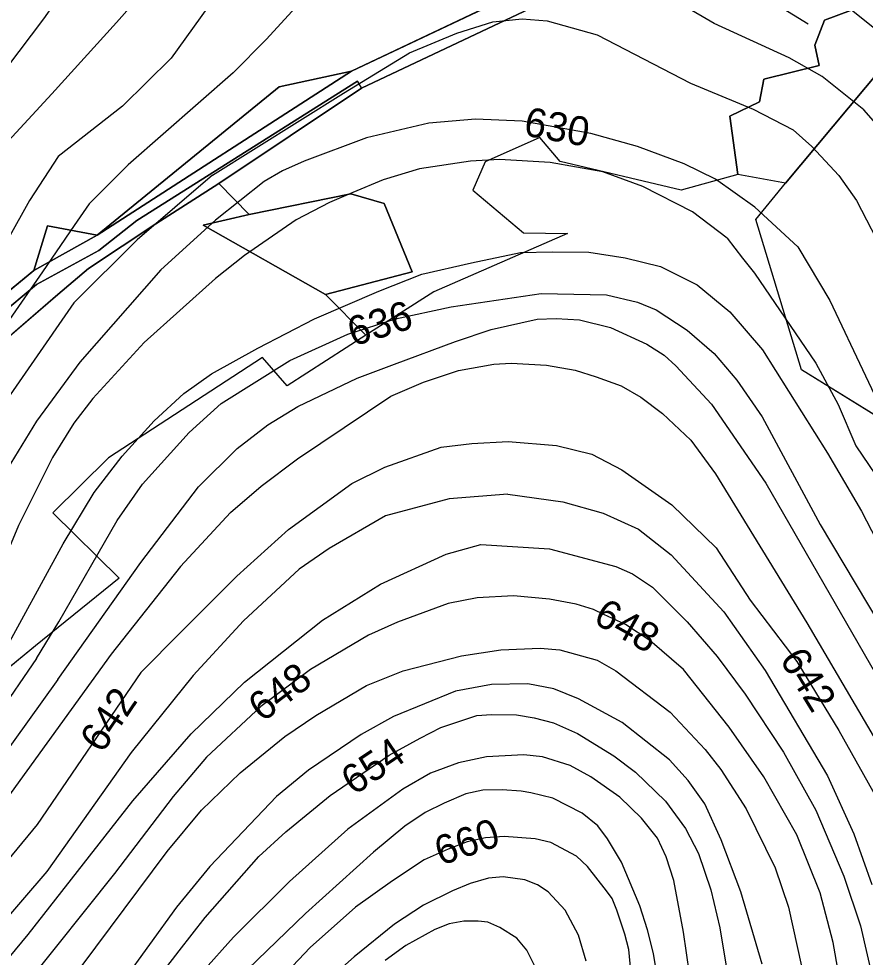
# Model space of a CAD drawing. Extents: x -709418 to -703832, y -1161719 to -1157826.
# Drawn here: x -706614.7 to -706381.5, y -1159816.4 to -1159557.8 of the extents above; entities that cross this region are included whole.
import ezdxf

# ---------------------------------------------------------------- set-up
doc = ezdxf.new("R2010")
doc.units = 0
for name, color, linetype in [('102_obvod PÚ', 7, 'Continuous'), ('120_vrstevnice hlavní', 7, 'Continuous'), ('121_vrstevnice hlavní_popis', 7, 'Continuous'), ('122_vrstevnice základní', 7, 'Continuous'), ('124_vrstevnice doplňková', 7, 'Continuous'), ('201_orná půda_KN', 7, 'Continuous'), ('206_TTP_KN', 7, 'Continuous'), ('210_ostatní plocha_KN', 7, 'Continuous')]:
    doc.layers.add(name, color=color, linetype=linetype)

msp = doc.modelspace()

# ---------------------------------------------------------------- linework, layer by layer
at = {"layer": '102_obvod PÚ'}
msp.add_lwpolyline([(-706367.74, -1159673.93), (-706399.11, -1159654.57), (-706411.64, -1159613.17), (-706403.46, -1159603.15), (-706416.61, -1159600.76), (-706432.22, -1159605.07), (-706465.56, -1159597.19), (-706471.14, -1159590.54), (-706486.23, -1159597.28), (-706489.67, -1159605.09), (-706475.68, -1159616.83), (-706463.55, -1159617.01), (-706500.37, -1159633.07), (-706519.13, -1159645.05), (-706540.75, -1159658.99), (-706547.56, -1159651.15), (-706589.97, -1159678.86), (-706605.34, -1159693.95), (-706587.09, -1159711.95), (-706610.14, -1159730.65), (-706648.39, -1159762.04), (-706648.03, -1159765), (-706661.44, -1159800.87), (-706686.33, -1159816.5)], dxfattribs=at)
at = {"layer": '120_vrstevnice hlavní'}
for points in [[(-706599.36, -1159545.61), (-706607.91, -1159557.89), (-706618.07, -1159571.37), (-706627.76, -1159583.84), (-706633.92, -1159592.08)], [(-706400.14, -1159620.68), (-706411.94, -1159609.75), (-706422.82, -1159602.06), (-706431.4, -1159597.76), (-706444.27, -1159593.05), (-706457.15, -1159589.47), (-706476.02, -1159586.04), (-706488.89, -1159585.47), (-706501.77, -1159586.61), (-706518.93, -1159590.61), (-706536.09, -1159597.05), (-706542.04, -1159599.71), (-706547.11, -1159602.7)], [(-706547.12, -1159602.7), (-706560.51, -1159613.3), (-706575.59, -1159626.97), (-706597.91, -1159652.48), (-706609.82, -1159668.71), (-706620.07, -1159685.26), (-706632.37, -1159707.7), (-706641.94, -1159724.9), (-706657.08, -1159747.29)], [(-706400.14, -1159620.68), (-706391.3, -1159635.45), (-706371.6, -1159676.97), (-706361.48, -1159695.78), (-706344.24, -1159720.85), (-706336.54, -1159733.39), (-706326.43, -1159752.2), (-706314.46, -1159777.28), (-706302.34, -1159796.09), (-706274.94, -1159816.35)], [(-706570.14, -1159708.76), (-706556.42, -1159693.85), (-706547.96, -1159686.64), (-706537.98, -1159679.11), (-706512.24, -1159661.86), (-706503.26, -1159658.01), (-706493.57, -1159654.74), (-706483.88, -1159653.03), (-706479.04, -1159652.74), (-706469.35, -1159653.31), (-706461.46, -1159654.68), (-706455.67, -1159656.45), (-706448.79, -1159658.94), (-706443.36, -1159662.08), (-706437.43, -1159666.56), (-706429.59, -1159673.97), (-706422.75, -1159683.24), (-706397.67, -1159724.27), (-706360.2, -1159788.11)], [(-706570.14, -1159708.76), (-706589.23, -1159732.95), (-706617.97, -1159772.72), (-706625.38, -1159783.55), (-706646.47, -1159811.2), (-706651.31, -1159815.9), (-706667.19, -1159827.83)], [(-706601.3, -1159824.16), (-706573.8, -1159787.26), (-706564.39, -1159775.86), (-706553.7, -1159765.6), (-706541.45, -1159755.62), (-706532.9, -1159749.78), (-706518.94, -1159741.52), (-706508.82, -1159737.53), (-706492.72, -1159733.39), (-706481.89, -1159731.68), (-706471.06, -1159731.26), (-706465.64, -1159731.68), (-706455.38, -1159734.53), (-706450.25, -1159737.53), (-706435.29, -1159748.93), (-706425.6, -1159759.19), (-706421.33, -1159764.74), (-706414.34, -1159775.57), (-706406.36, -1159791.82), (-706402.66, -1159802.65), (-706399.1, -1159818.89)], [(-706445.12, -1159830.57), (-706446.69, -1159814.33), (-706447.73, -1159810.04), (-706449.97, -1159803.5), (-706451.22, -1159800.26), (-706452.82, -1159798.09), (-706458.09, -1159791.39), (-706461.05, -1159788.6), (-706468.16, -1159784.84), (-706472.48, -1159783.84), (-706481.03, -1159783.12), (-706486.16, -1159783.55), (-706491.16, -1159784.59), (-706496.42, -1159786.69), (-706503.06, -1159789.61), (-706511.81, -1159795.38), (-706521.93, -1159802.65), (-706534.47, -1159813.76), (-706569.81, -1159851.09)]]:
    msp.add_lwpolyline(points, dxfattribs=at)
for points in [[(-706547.11, -1159602.7), (-706547.12, -1159602.7)], [(-706400.14, -1159620.68), (-706400.14, -1159620.68)]]:
    msp.add_open_spline(points, degree=1, dxfattribs=at)
at = {"layer": '122_vrstevnice základní'}
for points in [[(-706563.26, -1159531.12), (-706587.83, -1159558.83), (-706605.57, -1159578.52), (-706619.76, -1159593.82)], [(-706355.55, -1159626.14), (-706361.94, -1159611.03), (-706370.77, -1159595.62), (-706381.92, -1159582.89), (-706393.36, -1159573.74), (-706402.51, -1159568.59), (-706423.11, -1159559.15), (-706445.99, -1159545.71), (-706469.73, -1159535.7), (-706472.73, -1159534.84), (-706482.89, -1159532.27), (-706500.91, -1159529.83), (-706508.63, -1159530.41), (-706513.78, -1159532.41), (-706518.93, -1159535.55), (-706528.22, -1159543.42), (-706546.53, -1159563.58), (-706555.68, -1159572.74), (-706584.55, -1159598.12)], [(-706560.54, -1159551.57), (-706572.7, -1159568.73), (-706586.14, -1159581.89), (-706603.83, -1159595.76)], [(-706371.48, -1159566.59), (-706391.93, -1159550)], [(-706561.35, -1159600.93), (-706525.29, -1159578.32), (-706507.07, -1159567.2), (-706494.06, -1159561.76), (-706484.12, -1159558.68), (-706476.02, -1159557.86), (-706469.16, -1159558.44), (-706455.43, -1159562.3), (-706429.69, -1159575.6), (-706412.38, -1159582.75), (-706401.37, -1159588.47), (-706396.22, -1159593.05), (-706388.79, -1159601.05), (-706383.92, -1159607.92), (-706375.74, -1159623.67)], [(-706603.83, -1159595.77), (-706606.42, -1159599.69), (-706611.8, -1159607.89), (-706617.65, -1159618.43), (-706624.82, -1159629.82), (-706630.53, -1159637.86), (-706638.54, -1159648.76), (-706646.09, -1159659.46)], [(-706584.55, -1159598.12), (-706595.29, -1159608.85), (-706599.42, -1159614.83), (-706608.23, -1159627.56), (-706625.64, -1159652.63), (-706638.98, -1159674.38), (-706650.22, -1159691.76)], [(-706419.6, -1159618.3), (-706429.11, -1159611.06), (-706442.84, -1159604.06), (-706453.86, -1159600.05), (-706468.3, -1159597.48), (-706482.32, -1159596.62), (-706490.32, -1159597.05), (-706504.34, -1159599.2), (-706514.35, -1159602.25), (-706522.71, -1159605.69)], [(-706561.39, -1159600.96), (-706582.1, -1159618.78), (-706599.57, -1159636.08), (-706623.11, -1159670.05), (-706635.01, -1159687.29), (-706645.59, -1159703.84), (-706653.08, -1159715.45)], [(-706522.71, -1159605.69), (-706529.16, -1159608.45), (-706538.31, -1159613.27), (-706552.56, -1159623.1), (-706560.54, -1159629.37), (-706580.21, -1159647.04), (-706594.31, -1159662.43), (-706599.59, -1159669.27), (-706605.43, -1159678.68), (-706614.83, -1159697.49), (-706620.11, -1159710.03), (-706627.66, -1159725.7), (-706634.5, -1159738.24), (-706658.6, -1159767.11), (-706659.94, -1159769.66)], [(-706419.6, -1159618.3), (-706415.38, -1159623.8), (-706412.07, -1159627.95), (-706395.11, -1159652.74), (-706388.98, -1159664.14), (-706384.14, -1159675.54), (-706370.03, -1159696.34)], [(-706619.96, -1159734.25), (-706602.49, -1159702.51), (-706593.98, -1159688.37), (-706586.24, -1159678.38), (-706577.42, -1159668.63), (-706569.28, -1159661.08), (-706561.66, -1159655.71), (-706548.82, -1159648.57), (-706533.25, -1159640.54), (-706515.49, -1159632.87), (-706503.65, -1159628.2), (-706489.97, -1159625.06), (-706476.55, -1159622.19), (-706467.77, -1159622.06), (-706457.64, -1159622.11), (-706447.69, -1159623.68), (-706437.91, -1159626.09), (-706427.83, -1159631.14), (-706418.84, -1159638.59), (-706409.84, -1159649.07), (-706391.97, -1159677.54), (-706382.57, -1159693.5), (-706368.89, -1159720)], [(-706609.84, -1159734.13), (-706603.72, -1159723.99), (-706587.62, -1159696.06), (-706580.64, -1159686.09), (-706567.81, -1159671.84), (-706558.98, -1159663.86), (-706540.02, -1159652.03), (-706524.07, -1159644.76), (-706510.96, -1159640.49), (-706495.57, -1159637.21), (-706470.77, -1159633.51), (-706452.82, -1159633.93), (-706444.27, -1159635.93), (-706439.14, -1159638.06), (-706430.59, -1159643.62), (-706423.18, -1159650.03), (-706416.91, -1159657.44), (-706409.93, -1159667.56), (-706393.97, -1159697.2), (-706371.03, -1159735.67)], [(-706603.97, -1159739.91), (-706581.11, -1159707.62), (-706565.24, -1159686.8), (-706554.56, -1159676.25), (-706546.15, -1159669.7), (-706537.89, -1159664.71), (-706521.5, -1159656.87), (-706511.24, -1159653.03), (-706494.43, -1159646.76), (-706484.59, -1159643.48), (-706471.91, -1159640.63), (-706466.64, -1159640.38), (-706460.23, -1159640.77), (-706451.68, -1159642.91), (-706441.7, -1159647.47), (-706436.9, -1159650.54), (-706433.72, -1159653.45), (-706423.89, -1159664), (-706408.93, -1159685.8), (-706378.72, -1159738.24)], [(-706540.39, -1159698.57), (-706522.98, -1159685.85), (-706513.86, -1159681.35), (-706498.34, -1159675.87), (-706489.92, -1159674.9), (-706479.88, -1159674.35), (-706466.58, -1159675.43), (-706456.83, -1159677.83), (-706448.6, -1159682.08), (-706434.86, -1159691.78), (-706422.61, -1159703.61), (-706413.2, -1159718), (-706400.38, -1159734.96), (-706388.84, -1159753.91), (-706377.3, -1159774.43)], [(-706479.99, -1159688.87), (-706496.16, -1159690.14), (-706513.69, -1159694.76), (-706529.22, -1159703.78), (-706537.46, -1159709.46), (-706552.85, -1159723.7), (-706566.67, -1159738.81), (-706583.77, -1159760.04), (-706607, -1159792.81), (-706627.23, -1159816.18), (-706636.21, -1159825.73), (-706646.31, -1159834.43), (-706656.76, -1159841.61), (-706669.98, -1159850.17)], [(-706479.99, -1159688.87), (-706464.85, -1159690.97), (-706453.76, -1159694.05), (-706444.02, -1159698.47), (-706434.97, -1159705.59), (-706420.47, -1159721.28), (-706409.07, -1159737.38), (-706391.97, -1159766.45), (-706384.71, -1159782.41), (-706379.72, -1159796.38)], [(-706540.39, -1159698.57), (-706554.65, -1159711.42), (-706570.05, -1159726.83), (-706581.06, -1159737.95), (-706609.7, -1159779.85), (-706630.37, -1159804.93), (-706642.72, -1159818.11), (-706652.19, -1159826.59), (-706668.36, -1159837.21)], [(-706620.53, -1159820.17), (-706612.13, -1159810.2), (-706583.34, -1159773.29), (-706567.24, -1159754.91), (-706552.56, -1159740.66), (-706531.05, -1159723.56), (-706515.09, -1159713.59), (-706496.99, -1159705.32), (-706487.42, -1159702.71), (-706468.49, -1159703.9), (-706450.25, -1159708.74), (-706445.69, -1159710.74), (-706440.14, -1159714.44), (-706430.59, -1159723.99), (-706422.32, -1159733.54), (-706414.63, -1159743.94), (-706404.09, -1159759.9), (-706395.11, -1159775.86), (-706387.41, -1159794.1), (-706382.85, -1159807.78), (-706377.58, -1159830.57)], [(-706385.99, -1159837.42), (-706390.41, -1159812.34), (-706393.97, -1159798.66), (-706400.38, -1159782.7), (-706409.5, -1159766.74), (-706419.05, -1159753.06), (-706431.59, -1159737.1), (-706440.85, -1159729.12), (-706447.61, -1159724.78), (-706453.53, -1159721.99), (-706456.4, -1159720.64), (-706461.18, -1159719.14), (-706468.49, -1159717.72), (-706478.47, -1159716.86), (-706488.44, -1159717.43), (-706496.42, -1159719), (-706510.39, -1159724.13), (-706518.36, -1159727.69), (-706534.33, -1159737.1), (-706548, -1159747.36), (-706562.97, -1159761.32), (-706572.23, -1159772.15), (-706588.33, -1159793.38), (-706612.7, -1159823.88)], [(-706609.84, -1159734.13), (-706620.89, -1159750.1), (-706631.76, -1159764.56), (-706652.72, -1159788.19), (-706663.4, -1159798.43)], [(-706603.97, -1159739.91), (-706620.27, -1159762.59), (-706644.33, -1159791.1), (-706652.17, -1159799.08), (-706658.58, -1159804.5), (-706664.92, -1159809.65)], [(-706409.93, -1159818.32), (-706415.77, -1159798.37), (-706421.18, -1159784.12), (-706425.74, -1159774.15), (-706430.3, -1159767.73), (-706435.43, -1159762.04), (-706448.54, -1159751.78), (-706460.51, -1159745.22), (-706467.35, -1159742.51), (-706474.48, -1159741.09), (-706484.45, -1159741.23), (-706494.43, -1159743.08), (-706511.53, -1159750.06), (-706520.36, -1159755.05), (-706534.9, -1159764.89), (-706543.73, -1159772.15), (-706562.11, -1159791.39), (-706571.23, -1159802.65), (-706586.19, -1159823.17)], [(-706588.76, -1159838.27), (-706570.52, -1159814.62), (-706563.39, -1159805.5), (-706548.57, -1159788.68), (-706541.16, -1159781.84), (-706528.91, -1159771.87), (-706512.67, -1159760.75), (-706504.12, -1159756.05), (-706498.41, -1159753.11), (-706488.58, -1159749.85), (-706484.45, -1159749.5), (-706477.6, -1159749.6), (-706472.77, -1159750.49), (-706467.39, -1159751.86), (-706460.8, -1159754.77), (-706450.82, -1159760.9), (-706444.84, -1159765.46), (-706436.57, -1159773.43), (-706431.02, -1159780.99), (-706427.45, -1159787.83), (-706424.07, -1159797.88), (-706421.61, -1159808.35), (-706418.19, -1159828.86)], [(-706424.18, -1159860.78), (-706431.59, -1159809.49), (-706434.29, -1159795.24), (-706436.35, -1159788.73), (-706438.81, -1159783.59), (-706443.13, -1159778.14), (-706449.11, -1159772.29), (-706457.09, -1159766.74), (-706462.79, -1159763.6), (-706470.49, -1159761.18), (-706475.62, -1159760.61), (-706485.88, -1159761.18), (-706493.57, -1159762.89), (-706501.27, -1159765.74), (-706508.96, -1159770.16), (-706524.07, -1159781.13), (-706540.17, -1159795.52), (-706555.56, -1159810.91), (-706589.75, -1159849.1)], [(-706438.28, -1159824.88), (-706439.84, -1159815.43), (-706441.56, -1159808.92), (-706443.59, -1159802.27), (-706448.64, -1159790.23), (-706452.53, -1159783.84), (-706455.23, -1159780.2), (-706459.52, -1159776.71), (-706467.64, -1159772.58), (-706473.62, -1159771.15), (-706476.31, -1159770.66), (-706481.6, -1159770.3), (-706486.9, -1159770.41), (-706491.58, -1159771.44), (-706497.56, -1159774), (-706502.8, -1159776.57), (-706508.39, -1159780.27), (-706517.02, -1159787.48), (-706535.75, -1159804.36), (-706554.27, -1159822.31)], [(-706458.37, -1159817.48), (-706460.51, -1159810.34), (-706464.22, -1159803.5), (-706468.92, -1159798.37), (-706471.78, -1159796.5), (-706475.33, -1159795.09), (-706481.32, -1159794.24), (-706485.31, -1159794.67), (-706490.39, -1159796.13), (-706495.28, -1159798.09), (-706503.26, -1159802.08), (-706511.24, -1159807.35), (-706522.35, -1159816.32), (-706536.18, -1159828.58)], [(-706471.97, -1159819.98), (-706474.76, -1159814.47), (-706477.47, -1159811.2), (-706482.17, -1159808.2), (-706485.47, -1159806.78), (-706488.16, -1159806.49), (-706492.15, -1159806.49), (-706496.14, -1159807.21), (-706500.13, -1159808.77), (-706508.11, -1159813.19), (-706513.81, -1159817.32)]]:
    msp.add_lwpolyline(points, dxfattribs=at)
for points in [[(-706603.83, -1159595.76), (-706603.83, -1159595.77)], [(-706584.55, -1159598.12), (-706584.55, -1159598.12)], [(-706561.35, -1159600.93), (-706561.39, -1159600.96)], [(-706522.71, -1159605.69), (-706522.71, -1159605.69)], [(-706419.6, -1159618.3), (-706419.6, -1159618.3)]]:
    msp.add_open_spline(points, degree=1, dxfattribs=at)
at = {"layer": '124_vrstevnice doplňková'}
msp.add_lwpolyline([(-706397.22, -1159559.29), (-706425.97, -1159541.56), (-706443.7, -1159528.83), (-706454.57, -1159523.54), (-706463.44, -1159520.82), (-706475.45, -1159519.11), (-706483.46, -1159519.25), (-706509.8, -1159523.7), (-706518.07, -1159526.54), (-706526.79, -1159532.69)], dxfattribs=at)
at = {"layer": '201_orná půda_KN'}
msp.add_lwpolyline([(-706352.85, -1159517.15), (-706391.81, -1159525.36), (-706421.49, -1159531.99), (-706450.7, -1159537.9), (-706523.06, -1159572.25), (-706542.97, -1159576.56), (-706593.1, -1159617.45), (-706606.85, -1159614.86), (-706610.6, -1159627.21), (-706667.35, -1159673.86), (-706698.79, -1159694.01), (-706718.6, -1159677.79), (-706741.65, -1159667.26)], dxfattribs=at)
at = {"layer": '206_TTP_KN'}
for p, q in [((-706520.28, -1159576.96), (-706443.5, -1159540.62)), ((-706381.62, -1159554.1), (-706392.77, -1159558.2)), ((-706392.77, -1159558.2), (-706395.45, -1159565.09)), ((-706395.45, -1159565.09), (-706394.27, -1159570.71)), ((-706394.27, -1159570.71), (-706409.47, -1159574.49)), ((-706403.46, -1159603.15), (-706377.26, -1159571.71)), ((-706409.47, -1159574.49), (-706410.7, -1159580.72)), ((-706559.61, -1159603.19), (-706520.28, -1159576.96)), ((-706410.7, -1159580.72), (-706418.86, -1159584.64)), ((-706418.86, -1159584.64), (-706416.61, -1159600.76)), ((-706471.14, -1159590.54), (-706486.23, -1159597.28)), ((-706465.56, -1159597.19), (-706471.14, -1159590.54)), ((-706486.23, -1159597.28), (-706489.67, -1159605.09)), ((-706432.22, -1159605.07), (-706465.56, -1159597.19)), ((-706416.61, -1159600.76), (-706432.22, -1159605.07)), ((-706576.92, -1159614.35), (-706559.61, -1159603.19)), ((-706559.61, -1159603.19), (-706551.29, -1159611.78)), ((-706551.29, -1159611.78), (-706559.61, -1159603.19)), ((-706411.64, -1159613.17), (-706403.46, -1159603.15)), ((-706523.28, -1159606.09), (-706551.29, -1159611.78)), ((-706514.04, -1159608.7), (-706523.28, -1159606.09)), ((-706489.67, -1159605.09), (-706475.68, -1159616.83)), ((-706506.33, -1159627.57), (-706514.04, -1159608.7)), ((-706551.29, -1159611.78), (-706563.92, -1159614.73)), ((-706595.47, -1159626.69), (-706576.92, -1159614.35)), ((-706399.11, -1159654.57), (-706411.64, -1159613.17)), ((-706563.92, -1159614.73), (-706530.25, -1159633.79)), ((-706475.68, -1159616.83), (-706463.55, -1159617.01)), ((-706463.55, -1159617.01), (-706500.37, -1159633.07)), ((-706603.96, -1159633.83), (-706595.47, -1159626.69)), ((-706530.25, -1159633.79), (-706506.33, -1159627.57)), ((-706661.7, -1159683.54), (-706603.96, -1159633.83)), ((-706530.25, -1159633.79), (-706519.13, -1159645.05)), ((-706519.13, -1159645.05), (-706530.25, -1159633.79)), ((-706500.37, -1159633.07), (-706519.13, -1159645.05)), ((-706519.13, -1159645.05), (-706540.75, -1159658.99)), ((-706547.56, -1159651.15), (-706589.97, -1159678.86)), ((-706540.75, -1159658.99), (-706547.56, -1159651.15)), ((-706367.74, -1159673.93), (-706399.11, -1159654.57)), ((-706589.97, -1159678.86), (-706605.34, -1159693.95)), ((-706605.34, -1159693.95), (-706587.09, -1159711.95)), ((-706587.09, -1159711.95), (-706610.14, -1159730.65)), ((-706610.14, -1159730.65), (-706648.39, -1159762.04))]:
    msp.add_line(p, q, dxfattribs=at)
at = {"layer": '210_ostatní plocha_KN'}
for p, q in [((-706523.06, -1159572.25), (-706450.7, -1159537.9)), ((-706443.5, -1159540.62), (-706520.28, -1159576.96)), ((-706392.77, -1159558.2), (-706381.62, -1159554.1)), ((-706395.45, -1159565.09), (-706392.77, -1159558.2)), ((-706394.27, -1159570.71), (-706395.45, -1159565.09)), ((-706593.1, -1159617.45), (-706523.06, -1159572.25)), ((-706523.06, -1159572.25), (-706593.1, -1159617.45)), ((-706542.97, -1159576.56), (-706523.06, -1159572.25)), ((-706409.47, -1159574.49), (-706394.27, -1159570.71)), ((-706377.26, -1159571.71), (-706403.46, -1159603.15)), ((-706521.43, -1159575.02), (-706582.23, -1159613.45)), ((-706582.23, -1159613.45), (-706521.43, -1159575.02)), ((-706520.28, -1159576.96), (-706521.43, -1159575.02)), ((-706521.43, -1159575.02), (-706520.28, -1159576.96)), ((-706410.7, -1159580.72), (-706409.47, -1159574.49)), ((-706593.1, -1159617.45), (-706542.97, -1159576.56)), ((-706520.28, -1159576.96), (-706559.61, -1159603.19)), ((-706418.86, -1159584.64), (-706410.7, -1159580.72)), ((-706416.61, -1159600.76), (-706418.86, -1159584.64)), ((-706403.46, -1159603.15), (-706416.61, -1159600.76)), ((-706559.61, -1159603.19), (-706576.92, -1159614.35)), ((-706551.29, -1159611.78), (-706523.28, -1159606.09)), ((-706523.28, -1159606.09), (-706514.04, -1159608.7)), ((-706514.04, -1159608.7), (-706506.33, -1159627.57)), ((-706563.92, -1159614.73), (-706551.29, -1159611.78)), ((-706576.92, -1159614.35), (-706595.47, -1159626.69)), ((-706582.23, -1159613.45), (-706592.65, -1159621.73)), ((-706592.65, -1159621.73), (-706582.23, -1159613.45)), ((-706610.6, -1159627.21), (-706606.85, -1159614.86)), ((-706606.85, -1159614.86), (-706593.1, -1159617.45)), ((-706530.25, -1159633.79), (-706563.92, -1159614.73)), ((-706610.6, -1159627.21), (-706593.1, -1159617.45)), ((-706593.1, -1159617.45), (-706610.6, -1159627.21)), ((-706592.65, -1159621.73), (-706609.83, -1159631.09)), ((-706609.83, -1159631.09), (-706592.65, -1159621.73)), ((-706667.35, -1159673.86), (-706610.6, -1159627.21)), ((-706595.47, -1159626.69), (-706603.96, -1159633.83)), ((-706506.33, -1159627.57), (-706530.25, -1159633.79)), ((-706609.83, -1159631.09), (-706648.22, -1159662.85)), ((-706648.22, -1159662.85), (-706609.83, -1159631.09)), ((-706603.96, -1159633.83), (-706661.7, -1159683.54))]:
    msp.add_line(p, q, dxfattribs=at)

# ---------------------------------------------------------------- texts
at = {"layer": '121_vrstevnice hlavní_popis'}
for s, rotation, p in [('630', 349.565, (-706475.91, -1159589.91)), ('636', 17.2439, (-706522.62, -1159648.18)), ('648', 330.5697, (-706456.82, -1159724.11)), ('642', 301.5538, (-706405.29, -1159734.34)), ('648', 37.3487, (-706547.55, -1159751.86)), ('642', 55.9137, (-706591.77, -1159760.53)), ('654', 34.0195, (-706522.38, -1159772)), ('660', 18.9, (-706498.46, -1159791.26))]:
    msp.add_text(s, height=8, rotation=rotation, dxfattribs=at).set_placement(p)

doc.saveas('drawing.dxf')
